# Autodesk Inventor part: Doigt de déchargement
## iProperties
Created: 2001-06
Part Number: Doigt de déchargement
Material: Par défaut
Document SubType Name: Modélisation
Designer: Flavien MARTY
Control State: 0
Master: False
Checked Out: False
Shininess: 20.0
Length Units: 11269
Angle Units: 11279
Time Units: 11290
Mass Units: 11283
Length Display Precision: 3
Angle Display Precision: 2
Density: 0.0
Volumn: 0.0
Area: 0.0
PropertySet Name: Model Information
Author: Flavien MARTY
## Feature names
1. Extrusion1
2. Extrusion2
3. Extrusion3
4. Congé2 [Fillet]
5. Congé4 [Fillet]
